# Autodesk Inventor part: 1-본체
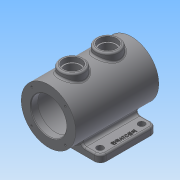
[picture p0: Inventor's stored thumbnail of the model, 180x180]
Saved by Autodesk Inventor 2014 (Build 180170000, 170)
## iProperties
Created: 2014-12
Part Number: 1-본체
Material: 일반
Document SubType Name: Modeling
Designer: Owner
Density: 1 g/cm^3
Appearance: 기본값
Author: Owner
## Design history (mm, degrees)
sketch "스케치1"
  geometry: L1 (-65, 47.5)-(65, 47.5); L2 (65, 47.5)-(65, -47.5); L3 (65, -47.5)-(-65, -47.5); L4 (-65, -47.5)-(-65, 47.5); 3 further points
  constraints: 8 end point, 2 midpoint, 2 parallel, 1 horizontal, 1 horizontal alignment, 1 perpendicular, 1 vertical alignment
  dimensions: "d0" = 95 distance between parallel lines of L3 L1; "d1" = 130 distance between parallel lines of L2 L4
extrude "돌출1" new body sketch "스케치1" distance "d2" = 12; taper "d3" = 0 deg
sketch "스케치2"
  geometry: L1 (65, 0)-(-65, 0) reference; C1 r 46 at (0, 50); 2 further points
  constraints: 1 centre point, 1 midpoint, 1 vertical alignment
  dimensions: "d4" = 92 diameter of C1; "d5" = 50 distance from line of L1 C1.centre
extrude "돌출2" join sketch "스케치2" stored distance "d6" = 140; taper "d7" = 0 deg
sketch "스케치3"
  geometry: L1 (-25.923, 12)-(-65, 12) reference; L2 (65, 12)-(25.923, 12) reference; L3 (65, 0)-(65, 12) reference; L4 (-65, 0)-(65, 0) reference; L5 (-65, 0)-(-65, 12) reference; L6 (-25.923, 12)-(-65, 12) reference; A1 r 5 centre (-38.884, 17) between (-38.884, 12) and (-35.072, 20.235); A2 r 5 centre (38.884, 17) between (35.072, 20.235) and (38.884, 12); A3 r 46 centre (0, 50) between (-25.923, 12) and (35.072, 20.235) reference; A4 r 46 centre (0, 50) between (-25.923, 12) and (25.923, 12) reference; 1 further point
  constraints: 6 point on circle, 4 tangent, 2 centre point, 2 point on line
  dimensions: "d8" = 5 radius of A1; "d9" = 5 radius of A2
extrude "돌출3" join sketch "스케치3" stored distance "d10" = 95; taper "d11" = 0 deg
node "작업 평면1"
sketch "스케치4"
  geometry: L1 (-46, -70)-(46, -70) reference; C1 r 20 at (0, -30); C2 r 20 at (0, 30); 1 further point
  constraints: 2 centre point, 2 vertical alignment
  dimensions: "d13" = 40 diameter of C1; "d14" = 40 diameter of C2; "d15" = 60 distance of C2.centre C1.centre; "d16" = 40 distance from line of C1.centre L1
extrude "돌출4" join sketch "스케치4" distance "d17" = 40; taper "d18" = 0 deg
hole "구멍1" diameter "d21" = 25; stored, may be unused: countersink angle "d25" = 90 deg, drill point angle "d27" = 0 deg; dims "d22" = 6, "d23" = 30, "d24" = 8, "d26" = 30, "d64" = 10, "d65" = 10
hole "구멍2" diameter "d30" = 25; stored, may be unused: countersink angle "d34" = 90 deg, drill point angle "d36" = 0 deg; dims "d31" = 6, "d32" = 30, "d33" = 8, "d35" = 40, "d66" = 10, "d67" = 10
hole "구멍3" diameter "d39" = 60; stored, may be unused: countersink angle "d43" = 90 deg, drill point angle "d45" = 0 deg; dims "d37" = 10, "d38" = 10, "d40" = 6, "d41" = 60, "d42" = 12, "d44" = 12
hole "구멍4" diameter "d48" = 75; stored, may be unused: countersink angle "d52" = 90 deg, drill point angle "d54" = 0 deg; dims "d46" = 10, "d47" = 10, "d49" = 6, "d50" = 60, "d51" = 12, "d53" = 116
hole "구멍5" diameter "d57" = 60; stored, may be unused: countersink angle "d61" = 90 deg, drill point angle "d63" = 0 deg; dims "d55" = 10, "d56" = 10, "d58" = 6, "d59" = 60, "d60" = 12, "d62" = 12
sketch "스케치5"
  geometry: L1 (65, -47.5)-(65, 47.5) reference; L2 (-52, 35)-(52, 35); L3 (52, 35)-(52, -35); 4 further points
  constraints: 4 end point, 3 horizontal alignment, 3 vertical alignment, 2 midpoint, 2 perpendicular
  dimensions: "d68" = 104 distance of L2.end L2.start; "d69" = 70 distance of L3.end L2.end
hole "구멍6" sketch "스케치5" at (-52, 35), (52, 35), (52, -35), (-52, -35) diameter "d70" = 11; stored, may be unused: countersink angle "d74" = 90 deg, drill point angle "d76" = 0 deg; dims "d71" = 6, "d72" = 60, "d73" = 12, "d75" = 12
sketch "스케치6"
  geometry: L1 (65, -47.5)-(65, 47.5) reference; C1 r 5.5 at (52, -35) reference; 2 further points
  constraints: 1 other
  dimensions: "d77" = 8 distance from line of point (57, 0) L1; "d78" = 35 vertical distance of point (57, 0) C1.centre
feature "엠보싱1" sketch "스케치6" dims "d0" = 95, "d1" = 130, "d79" = 1, "d80" = 0
sketch "스케치7" dims "d82" = 40
  geometry: L1 (0, 0)-(28.284, 28.284); L2 (0, 0)-(40, 0); C1 r 46 at (0, 0) reference; 1 further point
  constraints: 4 end point, 1 coincident, 1 equal length, 1 horizontal, 3 other
  dimensions: "d83" = 45 deg angle of L2 L1
hole "구멍7" sketch "스케치7" at (28.284, 28.284) diameter "d84" = 3.242; stored, may be unused: countersink angle "d88" = 90 deg, drill point angle "d90" = 118 deg; dims "d85" = 8, "d86" = 60, "d87" = 12, "d89" = 10
fillet "모깎기1" dims "d94" = 10
fillet "모깎기2" dims "d95" = 3
chamfer "모따기1" distance "d96" = 1; stored, may be unused: second distance "d97" = 2, angle "d98" = 45 deg
fillet "모깎기3" dims "d99" = 3
fillet "모깎기4" dims "d100" = 3
fillet "모깎기5" dims "d101" = 3
fillet "모깎기6" dims "d102" = 3
fillet "모깎기7" dims "d103" = 3
node "솔리드1"
pattern_circular "원형 패턴1" dims angle "d92" = 360 deg
mirror "대칭1"
node "투영된 루프1"
other parameters: "d12" = -106
